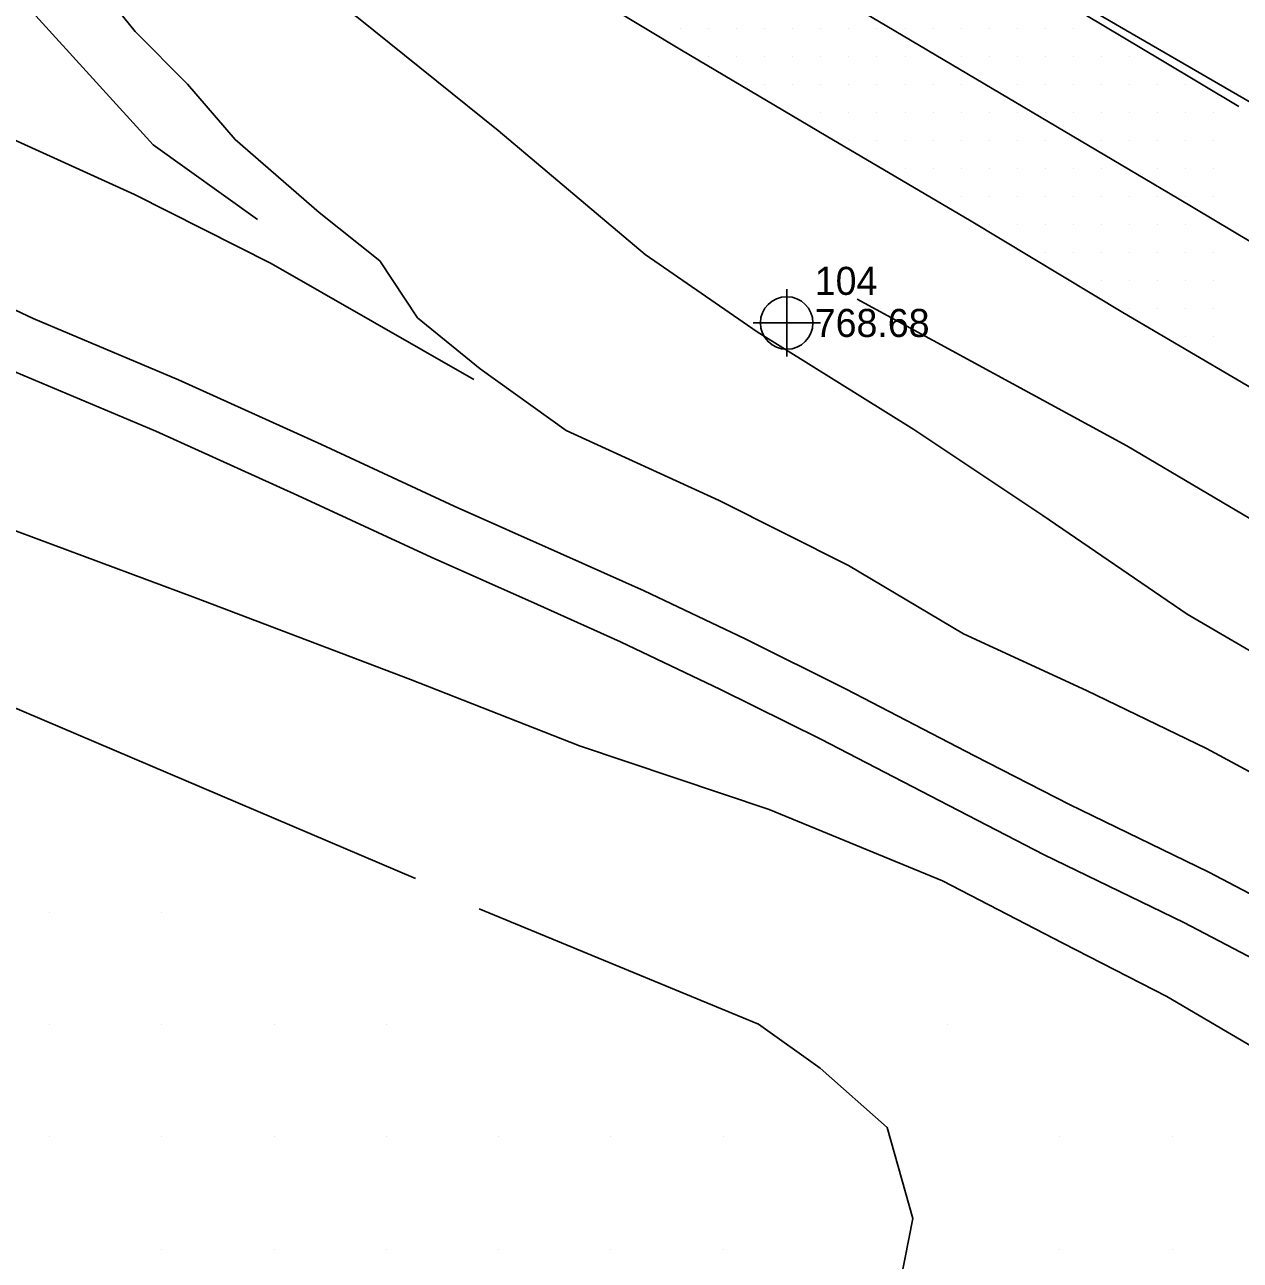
# Model space of a CAD drawing. Extents: x 1762120 to 1766775, y 709485 to 712965.
# Drawn here: x 1764452.8 to 1764561.1, y 710883.9 to 710994 of the extents above; entities that cross this region are included whole.
import ezdxf

# ---------------------------------------------------------------- set-up
doc = ezdxf.new("R2010")
doc.units = 0
for name, color, linetype in [('Cogo Default Point CELL', 7, 'Continuous'), ('COGO Default Point Elevation', 7, 'Continuous'), ('COGO Default Point Number', 7, 'Continuous'), ('Exist DTM QL2 LIDAR Elevation Point', 7, 'Continuous'), ('Exist DTM Scan Elevation Point', 7, 'Continuous'), ('Exist Roads EOP', 7, 'Continuous'), ('Exist Roads EOT', 7, 'Continuous'), ('PH Exist DTM Breakline', 7, 'Continuous')]:
    doc.layers.add(name, color=color, linetype=linetype)

msp = doc.modelspace()

# ---------------------------------------------------------------- linework, layer by layer
at = {"layer": 'Cogo Default Point CELL'}
for points in [[(1764520.71, 710970.47), (1764520.71, 710967.47)], [(1764517.71, 710967.47), (1764520.71, 710967.47)], [(1764520.71, 710967.47), (1764523.71, 710967.47)], [(1764520.71, 710967.47), (1764520.71, 710964.47)]]:
    msp.add_lwpolyline(points, dxfattribs=at)
msp.add_circle((1764520.71, 710967.47), 2.34, dxfattribs=at)
at = {"layer": 'Exist DTM QL2 LIDAR Elevation Point'}
for p, q in [((1764455.04, 710914.95), (1764455.04, 710914.95)), ((1764465.04, 710914.95), (1764465.04, 710914.95)), ((1764455.04, 710904.95), (1764455.04, 710904.95)), ((1764465.04, 710904.95), (1764465.04, 710904.95)), ((1764475.05, 710904.95), (1764475.05, 710904.95)), ((1764485.05, 710904.95), (1764485.05, 710904.95)), ((1764535.05, 710904.95), (1764535.05, 710904.95)), ((1764455.04, 710894.95), (1764455.04, 710894.95)), ((1764465.04, 710894.95), (1764465.04, 710894.95)), ((1764475.05, 710894.95), (1764475.05, 710894.95)), ((1764485.05, 710894.95), (1764485.05, 710894.95)), ((1764495.05, 710894.95), (1764495.05, 710894.95)), ((1764505.05, 710894.95), (1764505.05, 710894.95)), ((1764515.05, 710894.95), (1764515.05, 710894.95)), ((1764545.05, 710894.95), (1764545.05, 710894.95)), ((1764555.06, 710894.95), (1764555.06, 710894.95)), ((1764465.04, 710884.95), (1764465.04, 710884.95)), ((1764475.05, 710884.95), (1764475.05, 710884.95)), ((1764485.05, 710884.95), (1764485.05, 710884.95)), ((1764495.05, 710884.95), (1764495.05, 710884.95)), ((1764505.05, 710884.95), (1764505.05, 710884.95)), ((1764515.05, 710884.95), (1764515.05, 710884.95)), ((1764545.05, 710884.95), (1764545.05, 710884.95)), ((1764555.06, 710884.95), (1764555.06, 710884.95))]:
    msp.add_line(p, q, dxfattribs=at)
at = {"layer": 'Exist DTM Scan Elevation Point'}
for p, q in [((1764511.25, 710993.75), (1764511.25, 710993.75)), ((1764513.75, 710993.75), (1764513.75, 710993.75)), ((1764516.25, 710993.75), (1764516.25, 710993.75)), ((1764518.75, 710993.75), (1764518.75, 710993.75)), ((1764521.25, 710993.75), (1764521.25, 710993.75)), ((1764523.75, 710993.75), (1764523.75, 710993.75)), ((1764526.25, 710993.75), (1764526.25, 710993.75)), ((1764528.75, 710993.75), (1764528.75, 710993.75)), ((1764531.25, 710993.75), (1764531.25, 710993.75)), ((1764533.75, 710993.75), (1764533.75, 710993.75)), ((1764536.25, 710993.75), (1764536.25, 710993.75)), ((1764538.75, 710993.75), (1764538.75, 710993.75)), ((1764541.25, 710993.75), (1764541.25, 710993.75)), ((1764543.75, 710993.75), (1764543.75, 710993.75)), ((1764546.25, 710993.75), (1764546.25, 710993.75)), ((1764513.75, 710991.25), (1764513.75, 710991.25)), ((1764516.25, 710991.25), (1764516.25, 710991.25)), ((1764518.75, 710991.25), (1764518.75, 710991.25)), ((1764521.25, 710991.25), (1764521.25, 710991.25)), ((1764523.75, 710991.25), (1764523.75, 710991.25)), ((1764526.25, 710991.25), (1764526.25, 710991.25)), ((1764528.75, 710991.25), (1764528.75, 710991.25)), ((1764531.25, 710991.25), (1764531.25, 710991.25)), ((1764536.25, 710991.25), (1764536.25, 710991.25)), ((1764538.75, 710991.25), (1764538.75, 710991.25)), ((1764541.25, 710991.25), (1764541.25, 710991.25)), ((1764543.75, 710991.25), (1764543.75, 710991.25)), ((1764546.25, 710991.25), (1764546.25, 710991.25)), ((1764548.75, 710991.25), (1764548.75, 710991.25)), ((1764551.25, 710991.25), (1764551.25, 710991.25)), ((1764518.75, 710988.75), (1764518.75, 710988.75)), ((1764521.25, 710988.75), (1764521.25, 710988.75)), ((1764523.75, 710988.75), (1764523.75, 710988.75)), ((1764526.25, 710988.75), (1764526.25, 710988.75)), ((1764528.75, 710988.75), (1764528.75, 710988.75)), ((1764531.25, 710988.75), (1764531.25, 710988.75)), ((1764533.75, 710988.75), (1764533.75, 710988.75)), ((1764536.25, 710988.75), (1764536.25, 710988.75)), ((1764541.25, 710988.75), (1764541.25, 710988.75)), ((1764543.75, 710988.75), (1764543.75, 710988.75)), ((1764546.25, 710988.75), (1764546.25, 710988.75)), ((1764548.75, 710988.75), (1764548.75, 710988.75)), ((1764551.25, 710988.75), (1764551.25, 710988.75)), ((1764553.75, 710988.75), (1764553.75, 710988.75)), ((1764556.25, 710988.75), (1764556.25, 710988.75)), ((1764523.75, 710986.25), (1764523.75, 710986.25)), ((1764526.25, 710986.25), (1764526.25, 710986.25)), ((1764528.75, 710986.25), (1764528.75, 710986.25)), ((1764531.25, 710986.25), (1764531.25, 710986.25)), ((1764533.75, 710986.25), (1764533.75, 710986.25)), ((1764536.25, 710986.25), (1764536.25, 710986.25)), ((1764538.75, 710986.25), (1764538.75, 710986.25)), ((1764541.25, 710986.25), (1764541.25, 710986.25)), ((1764543.75, 710986.25), (1764543.75, 710986.25)), ((1764546.25, 710986.25), (1764546.25, 710986.25)), ((1764548.75, 710986.25), (1764548.75, 710986.25)), ((1764551.25, 710986.25), (1764551.25, 710986.25)), ((1764553.75, 710986.25), (1764553.75, 710986.25)), ((1764556.25, 710986.25), (1764556.25, 710986.25)), ((1764558.75, 710986.25), (1764558.75, 710986.25)), ((1764526.25, 710983.75), (1764526.25, 710983.75)), ((1764528.75, 710983.75), (1764528.75, 710983.75)), ((1764531.25, 710983.75), (1764531.25, 710983.75)), ((1764533.75, 710983.75), (1764533.75, 710983.75)), ((1764536.25, 710983.75), (1764536.25, 710983.75)), ((1764538.75, 710983.75), (1764538.75, 710983.75)), ((1764541.25, 710983.75), (1764541.25, 710983.75)), ((1764543.75, 710983.75), (1764543.75, 710983.75)), ((1764548.75, 710983.75), (1764548.75, 710983.75)), ((1764551.25, 710983.75), (1764551.25, 710983.75)), ((1764553.75, 710983.75), (1764553.75, 710983.75)), ((1764556.25, 710983.75), (1764556.25, 710983.75)), ((1764558.75, 710983.75), (1764558.75, 710983.75)), ((1764531.25, 710981.25), (1764531.25, 710981.25)), ((1764533.75, 710981.25), (1764533.75, 710981.25)), ((1764536.25, 710981.25), (1764536.25, 710981.25)), ((1764538.75, 710981.25), (1764538.75, 710981.25)), ((1764541.25, 710981.25), (1764541.25, 710981.25)), ((1764543.75, 710981.25), (1764543.75, 710981.25)), ((1764546.25, 710981.25), (1764546.25, 710981.25)), ((1764548.75, 710981.25), (1764548.75, 710981.25)), ((1764553.75, 710981.25), (1764553.75, 710981.25)), ((1764556.25, 710981.25), (1764556.25, 710981.25)), ((1764558.75, 710981.25), (1764558.75, 710981.25)), ((1764536.25, 710978.75), (1764536.25, 710978.75)), ((1764538.75, 710978.75), (1764538.75, 710978.75)), ((1764541.25, 710978.75), (1764541.25, 710978.75)), ((1764543.75, 710978.75), (1764543.75, 710978.75)), ((1764546.25, 710978.75), (1764546.25, 710978.75)), ((1764548.75, 710978.75), (1764548.75, 710978.75)), ((1764551.25, 710978.75), (1764551.25, 710978.75)), ((1764553.75, 710978.75), (1764553.75, 710978.75)), ((1764556.25, 710978.75), (1764556.25, 710978.75)), ((1764558.75, 710978.75), (1764558.75, 710978.75)), ((1764538.75, 710976.25), (1764538.75, 710976.25)), ((1764541.25, 710976.25), (1764541.25, 710976.25)), ((1764543.75, 710976.25), (1764543.75, 710976.25)), ((1764546.25, 710976.25), (1764546.25, 710976.25)), ((1764548.75, 710976.25), (1764548.75, 710976.25)), ((1764551.25, 710976.25), (1764551.25, 710976.25)), ((1764553.75, 710976.25), (1764553.75, 710976.25)), ((1764556.25, 710976.25), (1764556.25, 710976.25)), ((1764543.75, 710973.75), (1764543.75, 710973.75)), ((1764546.25, 710973.75), (1764546.25, 710973.75)), ((1764548.75, 710973.75), (1764548.75, 710973.75)), ((1764551.25, 710973.75), (1764551.25, 710973.75)), ((1764553.75, 710973.75), (1764553.75, 710973.75)), ((1764556.25, 710973.75), (1764556.25, 710973.75)), ((1764558.75, 710973.75), (1764558.75, 710973.75)), ((1764548.75, 710971.25), (1764548.75, 710971.25)), ((1764551.25, 710971.25), (1764551.25, 710971.25)), ((1764553.75, 710971.25), (1764553.75, 710971.25)), ((1764556.25, 710971.25), (1764556.25, 710971.25)), ((1764558.75, 710971.25), (1764558.75, 710971.25)), ((1764551.25, 710968.75), (1764551.25, 710968.75)), ((1764553.75, 710968.75), (1764553.75, 710968.75)), ((1764556.25, 710968.75), (1764556.25, 710968.75)), ((1764558.75, 710968.75), (1764558.75, 710968.75)), ((1764556.25, 710966.25), (1764556.25, 710966.25)), ((1764558.75, 710966.25), (1764558.75, 710966.25))]:
    msp.add_line(p, q, dxfattribs=at)
at = {"layer": 'Exist Roads EOP'}
for points in [[(1764561.99, 710987.14), (1764546.06, 710996.4), (1764533.24, 711004.17), (1764520.64, 711012.24), (1764508.1, 711020.44), (1764495.65, 711028.79), (1764483.21, 711037.05), (1764470.57, 711045.1), (1764458.18, 711053.51), (1764445.82, 711061.96), (1764433.57, 711070.46), (1764421.42, 711079.21), (1764409.42, 711088.09), (1764397.38, 711097), (1764385.52, 711106.15), (1764373.65, 711115.23), (1764362.05, 711124.7), (1764350.37, 711134.06), (1764338.81, 711143.53), (1764327.59, 711153.38), (1764319.58, 711159.9)], [(1764550.66, 710968.39), (1764537.13, 710976.54), (1764524.22, 710984.14), (1764511.34, 710991.79), (1764498.52, 710999.52), (1764485.77, 711007.41), (1764473.12, 711015.41), (1764460.52, 711023.55), (1764448.07, 711031.87), (1764435.73, 711040.36), (1764423.45, 711048.96), (1764411.28, 711057.69), (1764399.17, 711066.52), (1764387.19, 711075.51), (1764375.23, 711084.53), (1764363.45, 711093.78), (1764351.69, 711103.06), (1764340.06, 711112.5), (1764328.51, 711122.04), (1764317.04, 711131.67), (1764303.87, 711143.14)], [(1764550.66, 710968.39), (1764563.59, 710960.81), (1764576.62, 710953.42), (1764589.64, 710945.97), (1764602.64, 710938.52), (1764615.62, 710931.02), (1764628.68, 710923.66), (1764641.66, 710916.17), (1764654.79, 710908.93), (1764667.84, 710901.46), (1764682.64, 710893.08), (1764684.82, 710890.15), (1764691.27, 710876.76), (1764697.84, 710864.06), (1764702.16, 710851.09), (1764702.23, 710836.03), (1764701.57, 710822.11), (1764700.26, 710807.17), (1764699.3, 710792.2), (1764698.24, 710777.24), (1764697.25, 710762.27), (1764696.28, 710747.31), (1764695.25, 710732.34), (1764694.84, 710726.05)]]:
    msp.add_lwpolyline(points, dxfattribs=at)
at = {"layer": 'Exist Roads EOT'}
for points in [[(1764560.99, 710986.76), (1764554.18, 710990.83), (1764547.28, 710994.94), (1764534.11, 711002.82), (1764521.72, 711010.38), (1764501.09, 711023.22), (1764482.31, 711035.27), (1764468.68, 711044.31), (1764443.19, 711061.62), (1764426.14, 711073.72), (1764411.81, 711084.23), (1764394.61, 711097.2), (1764384.6, 711105), (1764373.59, 711113.61), (1764363.17, 711121.87), (1764347.35, 711134.65), (1764332.7, 711146.82), (1764318.57, 711159.13)], [(1764311.31, 711151.24), (1764322.79, 711141.35), (1764341.52, 711125.72), (1764364.51, 711107.26), (1764397.38, 711081.81), (1764416.02, 711067.97), (1764436.15, 711053.65), (1764459.67, 711037.71), (1764487.97, 711019.38), (1764506.65, 711007.8), (1764526.07, 710996.01), (1764555.53, 710978.58)], [(1764555.53, 710978.58), (1764580.03, 710963.97), (1764593.36, 710956.25), (1764611.66, 710945.65), (1764631.6, 710934.32), (1764655.54, 710920.71), (1764677.12, 710908.56), (1764690.9, 710900.88)]]:
    msp.add_lwpolyline(points, dxfattribs=at)
at = {"layer": 'PH Exist DTM Breakline'}
for points in [[(1764267.57, 711093.61), (1764272.8, 711105.2), (1764275.53, 711109.19), (1764283.59, 711106.31), (1764287.46, 711103.36), (1764291.92, 711094.45), (1764299.05, 711086.64), (1764317.02, 711076.5), (1764326.9, 711072.15), (1764337.83, 711065.26), (1764347.87, 711058.74), (1764354.41, 711053.83), (1764363.8, 711050.55), (1764380.06, 711036.17), (1764413.17, 711014.88), (1764424.06, 711007.25), (1764434.84, 711003.8), (1764447.25, 710998.07), (1764453.51, 710995.17), (1764464.26, 710983.34), (1764473.56, 710976.68)], [(1764276.31, 711085.09), (1764297.32, 711074.62), (1764311.22, 711065.76), (1764321.64, 711059.24), (1764332.34, 711051.83), (1764341.36, 711046.74), (1764349.16, 711043.14), (1764354.29, 711039.79), (1764363.76, 711032.65), (1764376.4, 711023.4), (1764390.2, 711016.06), (1764403.74, 711009.29), (1764415.37, 711001.6), (1764427.63, 710995.5), (1764440.05, 710989.49), (1764451.5, 710983.97), (1764462.6, 710978.92), (1764474.77, 710972.76), (1764492.83, 710962.42)], [(1764447.13, 711020.82), (1764457.18, 711013.61), (1764464.91, 711008.07), (1764472.71, 711002.1), (1764482.55, 710994.64), (1764495, 710984.61), (1764508.11, 710973.56), (1764518.08, 710966.67), (1764532.03, 710957.98), (1764543.53, 710950.32), (1764556.39, 710941.52), (1764567.88, 710934.82), (1764579.67, 710928.47), (1764589.78, 710924.01), (1764601.09, 710916.87), (1764612.28, 710910.56), (1764624.9, 710903.24), (1764637.31, 710896.64), (1764647, 710891.38), (1764654.43, 710886.92), (1764660.54, 710883.22)], [(1764456.62, 711000.94), (1764462.66, 710993.43), (1764467.33, 710988.75), (1764471.56, 710983.81), (1764479.05, 710977.32), (1764484.47, 710973), (1764487.82, 710967.93), (1764493.41, 710963.38), (1764501.05, 710957.9), (1764514.68, 710951.66), (1764526.2, 710945.86), (1764536.45, 710939.78), (1764547.41, 710934.71), (1764558.12, 710929.55), (1764569.83, 710923.23), (1764580.04, 710917.52), (1764590, 710911.02), (1764598.05, 710906.65), (1764606.39, 710902.63), (1764612.94, 710900.34), (1764619.3, 710896.92)], [(1764324.29, 710974.66), (1764334.39, 710976.87), (1764344.43, 710978.53), (1764360.26, 710978.17), (1764375.4, 710975.39), (1764388.03, 710972.71), (1764406.22, 710965.85), (1764420.55, 710960.37), (1764432.8, 710955.87), (1764446.47, 710951.01), (1764468.05, 710942.98), (1764487.18, 710935.71), (1764502.26, 710929.8), (1764519.16, 710924.1), (1764534.58, 710917.75), (1764545.3, 710912.2), (1764554.56, 710907.45), (1764565.59, 710900.99), (1764579.85, 710892.24)], [(1764445.06, 710971.88), (1764453.58, 710967.87), (1764466.52, 710962.4), (1764479.26, 710956.64), (1764491.09, 710951.15), (1764500.56, 710946.93), (1764508.01, 710943.59), (1764517.01, 710939.31), (1764526.01, 710934.84), (1764537.44, 710928.9), (1764545.89, 710924.55), (1764558.33, 710918.53), (1764567.89, 710913.51), (1764576.95, 710908.78), (1764585.56, 710904.16), (1764595.54, 710897.96), (1764602.25, 710894.03), (1764608.5, 710890.37), (1764610.97, 710888.6), (1764614.87, 710885.27), (1764617.59, 710882.73)], [(1764527, 710969.59), (1764551, 710956.51), (1764569.82, 710945.4), (1764577.46, 710939.21), (1764592.67, 710929.73), (1764608.29, 710920.23), (1764633.23, 710908.05), (1764642.73, 710903.51), (1764655.75, 710897.55), (1764660.63, 710895.22)], [(1764451.54, 710963.3), (1764464.52, 710957.82), (1764477.17, 710952.09), (1764489.02, 710946.6), (1764498.52, 710942.37), (1764505.91, 710939.05), (1764514.82, 710934.82), (1764523.75, 710930.38), (1764535.14, 710924.46), (1764543.66, 710920.08), (1764556.08, 710914.06), (1764565.57, 710909.08), (1764574.61, 710904.36), (1764583.05, 710899.83), (1764592.95, 710893.68), (1764599.72, 710889.71), (1764605.77, 710886.17), (1764607.89, 710884.66), (1764611.54, 710881.54)], [(1764376.62, 710958.67), (1764402.56, 710950.55), (1764423.68, 710943.43), (1764446.54, 710935.47), (1764487.63, 710917.97)], [(1764493.31, 710915.27), (1764518.2, 710905), (1764523.7, 710901.06), (1764529.65, 710895.77), (1764531.96, 710887.66), (1764527.71, 710866.08), (1764524.82, 710853.15), (1764522.71, 710844.52), (1764521.16, 710838.08)]]:
    msp.add_lwpolyline(points, dxfattribs=at)

# ---------------------------------------------------------------- texts
at = {"layer": 'COGO Default Point Elevation'}
msp.add_text('768.68', height=2.5, dxfattribs=at).set_placement((1764523.21, 710966.22))
at = {"layer": 'COGO Default Point Number'}
msp.add_text('104', height=2.5, dxfattribs=at).set_placement((1764523.21, 710969.97))

doc.saveas('drawing.dxf')
